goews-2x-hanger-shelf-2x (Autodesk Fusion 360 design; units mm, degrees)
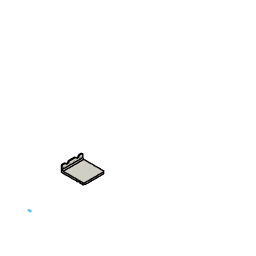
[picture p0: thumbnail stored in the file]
base_feature "Base Feature2"
base_feature "Base Feature1" bodies "Double Plate Blank"
delete_face "DeleteFace1"
split "Split1" bodies "Double Plate Blank (1)"
delete_face "DeleteFace2"
move_face "MoveFace1"
fillet "Fillet1" radius 3.75
combine "Combine1" bodies "Double Plate Blank"
chamfer "Chamfer1" distance 4
move_face "MoveFace2"
extrude "Extrude1" cut sketch "Reconstructed-Sketch2" blind -1060
named bodies: "Double Plate Blank", "Double Plate Blank (1)"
